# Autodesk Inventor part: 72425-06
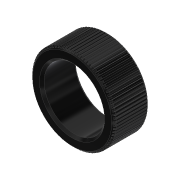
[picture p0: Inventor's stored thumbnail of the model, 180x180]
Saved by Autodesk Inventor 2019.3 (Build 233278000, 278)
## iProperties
Created: 2012-10
Part Number: 72425-06
Material: Ogólny
Document SubType Name: Modeling
Designer: CADENGINEERING4
Density: 1 g/cm^3
Appearance: Gładki — czarny
Author: CADENGINEERING4
Revision Number: ÈÎºÎ
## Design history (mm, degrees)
feature "ÊäÈë1"
node "Bryła1"
